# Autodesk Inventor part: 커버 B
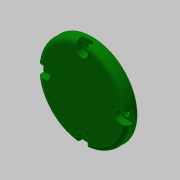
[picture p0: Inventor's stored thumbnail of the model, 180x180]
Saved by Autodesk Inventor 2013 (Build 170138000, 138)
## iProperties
Created: 2019-05
Part Number: 커버 B
Material: 알루미늄 6061
Document SubType Name: Modeling
Designer: mduedu
Density: 2.71 g/cm^3
Mass: 59.4974 g
Surface Area: 80.458 cm^2
Volume: 21.9548 cm^3
Author: mduedu
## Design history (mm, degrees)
sketch "스케치1"
  geometry: C1 r 31 at (0, 0); 1 further point
  constraints: 1 centre point, 1 coincident
  dimensions: "d0" = 62 diameter of C1
extrude "돌출1" new body sketch "스케치1" distance "d1" = 7; taper "d2" = 0 deg
sketch "스케치3"
  geometry: C1 r 20 at (0, 0); 1 further point
  constraints: 1 centre point, 1 coincident
  dimensions: "d7" = 40 diameter of C1
extrude "돌출3" join sketch "스케치3" distance "d8" = 4; taper "d9" = 0 deg
sketch "스케치4"
  geometry: C1 r 17 at (0, 0); 1 further point
  constraints: 1 centre point, 1 coincident
  dimensions: "d10" = 34 diameter of C1
extrude "돌출4" cut sketch "스케치4" distance "d11" = 3; taper "d12" = 0 deg
fillet "모깎기3" dims "d20" = 3
fillet "모깎기4" dims "d21" = 3
chamfer "모따기1" distance "d22" = 1; stored, may be unused: second distance "d23" = 2, angle "d24" = 45 deg
sketch "스케치7" dims "d25" = 52
  geometry: L1 (-4, 26)-(-4, 30.741); L2 (4, 26)-(4, 30.741); A1 r 4 centre (0, 26) between (-4, 26) and (4, 26); A2 r 31 centre (0, 0) between (4, 30.741) and (-4, 30.741); 3 further points
  constraints: 4 end point, 4 point on circle, 2 centre point, 2 coincident, 2 tangent, 2 vertical alignment, 1 parallel, 1 vertical, 4 other
  dimensions: "d26" = 8 distance between parallel lines of L2 L1
extrude "돌출7" cut sketch "스케치7" distance "d27" = 4.4; taper "d28" = 0 deg
sketch "스케치8" dims "d36" = 52
  geometry: 6 further points
  constraints: 2 vertical alignment, 1 coincident, 7 other
  dimensions: "d39" = 360 deg dimension on point (0, 0) point (0, 26) (derived)
sketch "스케치9"
  geometry: 4 further points
  constraints: 4 other
hole "구멍1" sketch "스케치9" at (0, 52), (-26, 26), (26, 26), (0, 0) diameter "d41" = 4.5; stored, may be unused: countersink angle "d45" = 90 deg, drill point angle "d47" = 0 deg; dims "d42" = 6, "d43" = 4, "d44" = 2, "d46" = 8
node "솔리드1"
pattern_circular "원형 패턴1" dims angle "d30" = 360 deg
